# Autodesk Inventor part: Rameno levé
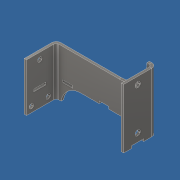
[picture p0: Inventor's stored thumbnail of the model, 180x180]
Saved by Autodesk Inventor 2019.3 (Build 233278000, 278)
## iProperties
Created: 2019-02
Part Number: Rameno levé
Material: Nerezová ocel, austenitická
Document SubType Name: Plech
Designer: B-hon
Density: 8 g/cm^3
Sheet Metal Rule: Výchozí_mm
Appearance: Pololeštěná
Author: B-hon
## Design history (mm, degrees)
node "Plocha3"
  sketch "Náčrt4"
    geometry: L1 (0, 0)-(125, 0); L2 (125, 0)-(125, 95); L3 (125, 95)-(0, 95); L4 (0, 95)-(0, 0)
    constraints: 8 end point, 2 parallel, 1 horizontal, 1 perpendicular
    dimensions: "d21" = 125 distance of L3.end L2.end; "d22" = 95 distance of L2.end L1.end
node "Obruba2"
node "Obruba3"
sketch "Náčrt7"
  geometry: L1 (-8.449, 60)-(-3.667, 60); L2 (-3.667, 60)-(-3.667, 60); L3 (-3.667, 60)-(116, 60); L4 (116, 60)-(116, 100.088); L5 (116, 100.088)-(-8.681, 99.353); L6 (-8.681, 99.353)-(-8.449, 60); L7 (6, 95)-(6, 0) reference; L8 (119, 0)-(119, 95) reference; L9 (119, 0)-(6, 0) reference; 1 further point
  constraints: 12 end point, 4 perpendicular, 1 horizontal
  dimensions: "d45" = 3 distance between parallel lines of L8 L4; "d46" = 60 distance between parallel lines of L9 L3; "d47" = 60 distance between parallel lines of L9 L1
extrude "Vysunutí1" cut sketch "Náčrt7" stored distance "d48" = 100; taper "d49" = 0 deg
fillet "Zaoblení2" dims "d51" = 35
sketch "Náčrt8"
  geometry: L1 (9, 21)-(200.584, 21); L2 (200.584, 21)-(200.584, -6.662); L3 (200.584, -6.662)-(9, -6.662); L4 (9, -6.662)-(9, 21); L5 (81, 60)-(6, 60) reference; L6 (6, 60)-(6, 0) reference; 1 further point
  constraints: 8 end point, 2 parallel, 1 horizontal, 1 perpendicular
  dimensions: "d52" = 39 distance between parallel lines of L5 L1; "d53" = 3 distance between parallel lines of L6 L4
extrude "Vysunutí2" cut sketch "Náčrt8" stored distance "d54" = 100; taper "d55" = 0 deg
fillet "Zaoblení3" dims "d56" = 25
sketch "Náčrt9"
  geometry: L1 (0, 0)-(0, 95) reference; L2 (34, 0)-(0, 0) reference; 5 further points
  constraints: 1 horizontal alignment
  dimensions: "d57" = 6 distance from line of L1 point (6, 7); "d58" = 21 distance of point (27, 7) point (6, 7); "d59" = 7 distance from line of L2 point (6, 7); "d60" = 45 vertical distance of point (27, 7) point (16.5, 52); "d61" = 10.5 horizontal distance of point (27, 7) point (16.5, 52) (= 0.5 x d58)
hole "Díra1" sketch "Náčrt9" at (16.5, 52), (27, 7), (6, 7) diameter "d62" = 5.5; stored, may be unused: countersink angle "d66" = 90 deg, drill point angle "d68" = 118 deg; dims "d63" = 12, "d64" = 4, "d65" = 2, "d67" = 3 (= Tloušťka)
sketch "Náčrt10"
  geometry: L1 (0, 0)-(35, 0) reference; C1 r 2.75 at (28, -88) reference; C2 r 2.75 at (7, -88) reference; C3 r 2.75 at (17.5, -43) reference; 3 further points
  constraints: 2 vertical alignment
  dimensions: "d69" = 9 distance from line of point (17.5, -9) L1; "d70" = 52 distance of point (17.5, -61) point (17.5, -9)
hole "Díra2" sketch "Náčrt10" at (17.5, -61), (17.5, -9) diameter "d71" = 6.6; stored, may be unused: countersink angle "d75" = 90 deg, drill point angle "d77" = 118 deg; dims "d72" = 12, "d73" = 4, "d74" = 2, "d76" = 3 (= Tloušťka)
sketch "Náčrt15"
  geometry: L1 (-119, 21)-(-33.678, 21) reference; L2 (-114, 24)-(-102, 24); L3 (-102, 24)-(-102, 21); L4 (-102, 21)-(-114, 21); L5 (-114, 21)-(-114, 24); L6 (-119, 95)-(-119, 21) reference; 1 further point
  constraints: 8 end point, 2 parallel, 1 horizontal, 1 perpendicular, 1 point on line
  dimensions: "d104" = 12 distance of L3.end L4.end; "d105" = 3 distance of L2.end L3.end; "d106" = 5 distance between parallel lines of L6 L5
extrude "Vysunutí7" cut sketch "Náčrt15" distance "d107" = 300; taper "d108" = 0 deg
pattern_linear "Obdélníkové pole3" dims "d111" = 45.5
sketch "Náčrt16"
  geometry: L1 (10, -71)-(25, -71); L2 (25, -71)-(25, -74); L3 (25, -74)-(10, -74); L4 (10, -74)-(10, -71); L5 (0, -74)-(35, -74) reference; L6 (-3, -74)-(-3, 0) reference; 2 further points
  constraints: 8 end point, 2 parallel, 1 horizontal, 1 perpendicular
  dimensions: "d112" = 0 distance between parallel lines of L5 L3; "d113" = 3 distance of L1.end L2.end; "d114" = 15 distance of L2.end L3.end; "d115" = 13 distance between parallel lines of L6 L4
extrude "Vysunutí8" cut sketch "Náčrt16" stored distance "d116" = 500; taper "d117" = 0 deg
node "Těleso3"
feature "Deska4" dims "d23" = 3 (= Tloušťka)
sketch "Náčrt5"
  geometry: L1 through (47.5, 0) direction (-1, 0); L2 through (0, -20) direction (0, -1); L3 (0, -40)-(95, -40); L4 (95, -40)-(95, 0)
  constraints: 6 end point, 1 horizontal, 1 perpendicular, 1 vertical
feature "Deska5" dims "d23" = 3 (= Tloušťka), "d24" = 3 (= ŠířkaVýštipu), "d25" = 1.5 (= HloubkaVýštipu), "d26" = 6 (= MinimálníZbytek), "d27" = 3 (= PřechodovýPoloměr), "d28" = 40, "d29" = -90 deg, "d30" = 3 (= PoloměrOhybu), "d31" = 12 (= VelikostRohovéhoVýštipu), "d32" = 3 (= VelikostMezery), "d33" = 3 (= VelikostJacobihoPoloměru), "MezeraVystřižení" = 0.01
feature "Ohyb2" dims "d23" = 3 (= Tloušťka), "d24" = 3 (= ŠířkaVýštipu), "d25" = 1.5 (= HloubkaVýštipu), "d26" = 6 (= MinimálníZbytek), "d27" = 3 (= PřechodovýPoloměr), "d28" = 40, "d29" = -90 deg, "d30" = 3 (= PoloměrOhybu), "MezeraVystřižení" = 0.01
feature "Roh2" dims "d28" = 40, "d29" = -90 deg, "d31" = 12 (= VelikostRohovéhoVýštipu), "d32" = 3 (= VelikostMezery), "d33" = 3 (= VelikostJacobihoPoloměru)
sketch "Náčrt6"
  geometry: L1 through (47.5, 0) direction (-1, 0); L2 through (0, -20.5) direction (0, -1); L3 (0, -41)-(95, -41); L4 (95, -41)-(95, 0)
  constraints: 6 end point, 1 horizontal, 1 perpendicular, 1 vertical
feature "Deska6" dims "d23" = 3 (= Tloušťka), "d34" = 3 (= ŠířkaVýštipu), "d35" = 1.5 (= HloubkaVýštipu), "d36" = 6 (= MinimálníZbytek), "d37" = 3 (= PřechodovýPoloměr), "d38" = 41, "d39" = -90 deg, "d40" = 3 (= PoloměrOhybu), "d41" = 12 (= VelikostRohovéhoVýštipu), "d42" = 3 (= VelikostMezery), "d43" = 3 (= VelikostJacobihoPoloměru), "MezeraVystřižení" = 0.01
feature "Ohyb3" dims "d23" = 3 (= Tloušťka), "d34" = 3 (= ŠířkaVýštipu), "d35" = 1.5 (= HloubkaVýštipu), "d36" = 6 (= MinimálníZbytek), "d37" = 3 (= PřechodovýPoloměr), "d38" = 41, "d39" = -90 deg, "d40" = 3 (= PoloměrOhybu), "MezeraVystřižení" = 0.01
feature "Roh3" dims "d38" = 41, "d39" = -90 deg, "d41" = 12 (= VelikostRohovéhoVýštipu), "d42" = 3 (= VelikostMezery), "d43" = 3 (= VelikostJacobihoPoloměru)
other parameters: "Tloušťka" = 3 (derived), "KSoučinitel" = 4.4, "PoloměrOhybu" = 3 (= Tloušťka), "ŠířkaVýštipu" = 3 (= Tloušťka), "HloubkaVýštipu" = 1.5 (= 0.5 x Tloušťka), "VelikostRohovéhoVýštipu" = 12 (= 4 x Tloušťka), "MinimálníZbytek" = 6 (= 2 x Tloušťka), "PřechodovýPoloměr" = 3 (= PoloměrOhybu), "VelikostJacobihoPoloměru" = 3 (= PoloměrOhybu), "VelikostMezery" = 3 (= Tloušťka)
